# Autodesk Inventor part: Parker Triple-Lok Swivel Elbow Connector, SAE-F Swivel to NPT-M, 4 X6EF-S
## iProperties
Shininess: 27.0
Length Units: 11272
Angle Units: 11279
Time Units: 11290
Mass Units: 11286
Length Display Precision: 3
Angle Display Precision: 2
Category: Hydraulics
Created: 2001-03
Part Number: Parker Triple-Lok Swivel Elbow Connector, SAE-F Swivel to NPT-M, 4 X6EF-S
Material: Steel, Mild
Catalog Web Link: http://www.aeroquip.com
Description: Parker Triple-Lok Swivel Elbow Connector, SAE-F Swivel to NPT-M, 4 X6EF-S
Document SubType Name: Modeling
Designer: QBZ
Density: 7.859999999999999
Volumn: 12.768401423356869
Area: 73.09805400316779
PropertySet Name: Model Information
Control State: 0
Master: False
Checked Out: False
Last Check In By: Charles Bliss
Last Check In Date: 2003-09-27
Title: JIC Swivel Elbow 90deg
Subject: Hydraulic Adapters
Author: QBZ
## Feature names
1. Male Body [Extrusion]
2. Female Body [Extrusion]
3. Revolution1
4. Female JIC [Revolution]
5. Hex [Extrusion]
6. Fillet1
7. Revolution6
8. Mirror1
9. Hole3
10. Extrusion4
11. Hole4
